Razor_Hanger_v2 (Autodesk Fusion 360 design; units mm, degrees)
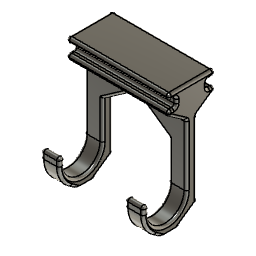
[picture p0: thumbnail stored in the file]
sketch "Skizze1" plane through (0, 0, 0) normal (1, 0, 0) x axis (0, 1, 0)
  line L1 (0, 24) -> (0, 0)
  line L2 (-7, 28.9015) -> (0, 24)
  line L3 (-7, 30.5515) -> (-7, 28.9015)
  line L4 (-4, 30.5515) -> (-7, 30.5515)
  line L5 (-4, 34.0515) -> (-4, 30.5515)
  line L6 (-7, 34.0515) -> (-4, 34.0515)
  line L7 (-7, 36.2015) -> (-7, 34.0515)
  line L8 (11, 36.2015) -> (-7, 36.2015)
  line L9 (11, 34.0515) -> (11, 36.2015)
  line L10 (8, 34.0515) -> (11, 34.0515)
  line L11 (8, 30.5515) -> (8, 34.0515)
  line L12 (11, 30.5515) -> (8, 30.5515)
  line L13 (11, 28.9015) -> (11, 30.5515)
  line L14 (4, 24) -> (11, 28.9015)
  line L15 (4, 0.1188) -> (4, 24)
  line L16 (4, -5.3761) -> (4, 0.1188)
  line L17 (-10.653, -10) -> (-2.6036, -10)
  line L18 (-12.449, -8.7424) -> (-10.653, -10)
  line L19 (-17, 2) -> (-17, 0)
  line L20 (-15, 0) -> (-15, 2)
  line L21 (4, -5.3761) -> (-2.6036, -10)
  arc A1 centre (-6.3275, 0) radius 10.6725 clockwise from (-12.449, -8.7424) to (-17, 0)
  arc A2 centre (-16, 2) radius 1 clockwise from (-17, 2) to (-15, 2)
  arc A3 centre (-7.5, 0) radius 7.5 clockwise from (0, 0) to (-15, 0)
  point P1 (0, 0)
  point P2 (0, 0)
  point P26 (0, 0)
  point P3 (0, 24)
  point P16 (4, 24)
  point P4 (-7, 28.9015)
  point P15 (11, 28.9015)
  point P6 (-4, 30.5515)
  point P7 (-4, 34.0515)
  point P8 (-7, 34.0515)
  point P20 (-17, 0)
  point P22 (-17, 2)
  point P27 (-7.5, 0)
  point P9 (-7, 36.2015)
  point P5 (-7, 30.5515)
  point P24 (-16, 2)
  coincident P1 P2
  vertical L1
  perpendicular L3 L4
  perpendicular L4 L5
  perpendicular L5 L6
  perpendicular L6 L7
  perpendicular L5 L8
  perpendicular L8 L9
  perpendicular L9 L10
  perpendicular L10 L11
  perpendicular L11 L12
  perpendicular L12 L13
  perpendicular L16 L17
  equal L4 L12
  collinear L9 L13
  collinear L3 L7
  equal L5 L11
  collinear L4 L12
  tangent L18 A1
  vertical L19
  tangent L19 A2
  tangent A2 L20
  vertical L20
  coincident P1 P26
  tangent L20 A3
  tangent L1 A3
  equal L19 L20
  tangent A1 L19
  horizontal L8
  horizontal P3 P16
  equal L2 L14
  horizontal P4 P15
  horizontal L17
  dimension "d1" distance P6 P7 = 3.5
  dimension "d3" distance L5 L11 = 12
  dimension "d4" distance L1 L15 = 4
  dimension "d6" distance P7 P8 = 3
  dimension "d7" distance P1 L17 = 10
  dimension "d8" angle L17 L18 = 35
  dimension "d9" distance L1 L20 = 15
  dimension "d10" distance P20 P22 = 2
  dimension "d11" distance L19 L20 = 2
  dimension "d12" distance L18 P27 = 10
  dimension "d19" angle L1 L2 = 125
  dimension "d20" distance P8 P9 = 2.15
  dimension "d21" angle L17 L21 = 35
  dimension "d22" distance P27 L21 = 11
  dimension "d31" distance P4 P5 = 1.65
  dimension "d36" distance P3 P24 = 22
extrude "Extrusion1" new body sketch "Skizze1" distance 40
sketch "Skizze3" plane through (0, 11, 0) normal (0, 1, 0) x axis (-1, 0, 0)
  line L1 (-20, 30.5515) -> (20, 30.5515)
  line L2 (-20, 28.9015) -> (-20, 30.5515)
  line L3 (20, 28.9015) -> (-20, 28.9015)
  line L4 (20, 30.5515) -> (20, 28.9015)
  line L5 (13, -10) -> (-13, -10)
  line L6 (13, 14.8973) -> (13, -10)
  line L7 (-13, -10) -> (-13, 14.8973)
  line L8 (0, 24) -> (-13, 14.8973)
  line L9 (13, 14.8973) -> (0, 24)
  line L10 (-20, 24) -> (20, 24)
  line L11 (-20, -10) -> (20, -10)
  point P1 (0, 0)
  point P10 (0, 24)
  point P7 (13, -10)
  point P8 (13, 14.8973)
  point P9 (-13, 14.8973)
  point P5 (20, 28.9015)
  horizontal L5
  vertical L6
  vertical L7
  equal L8 L9
  vertical P1 P10
  coincident P10 L10
  coincident P7 L11
  horizontal P8 P9
  dimension "d23" angle L3 L9 = 35
  dimension "d25" distance P5 L6 = 7
extrude "Extrusion3" cut sketch "Skizze3" profile of L5 L6 L7 L8 L9 L11 no distance stored
fillet "Abrundung1" radius 1
fillet "Abrundung3" radius 1
fillet "Abrundung2" radius 1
